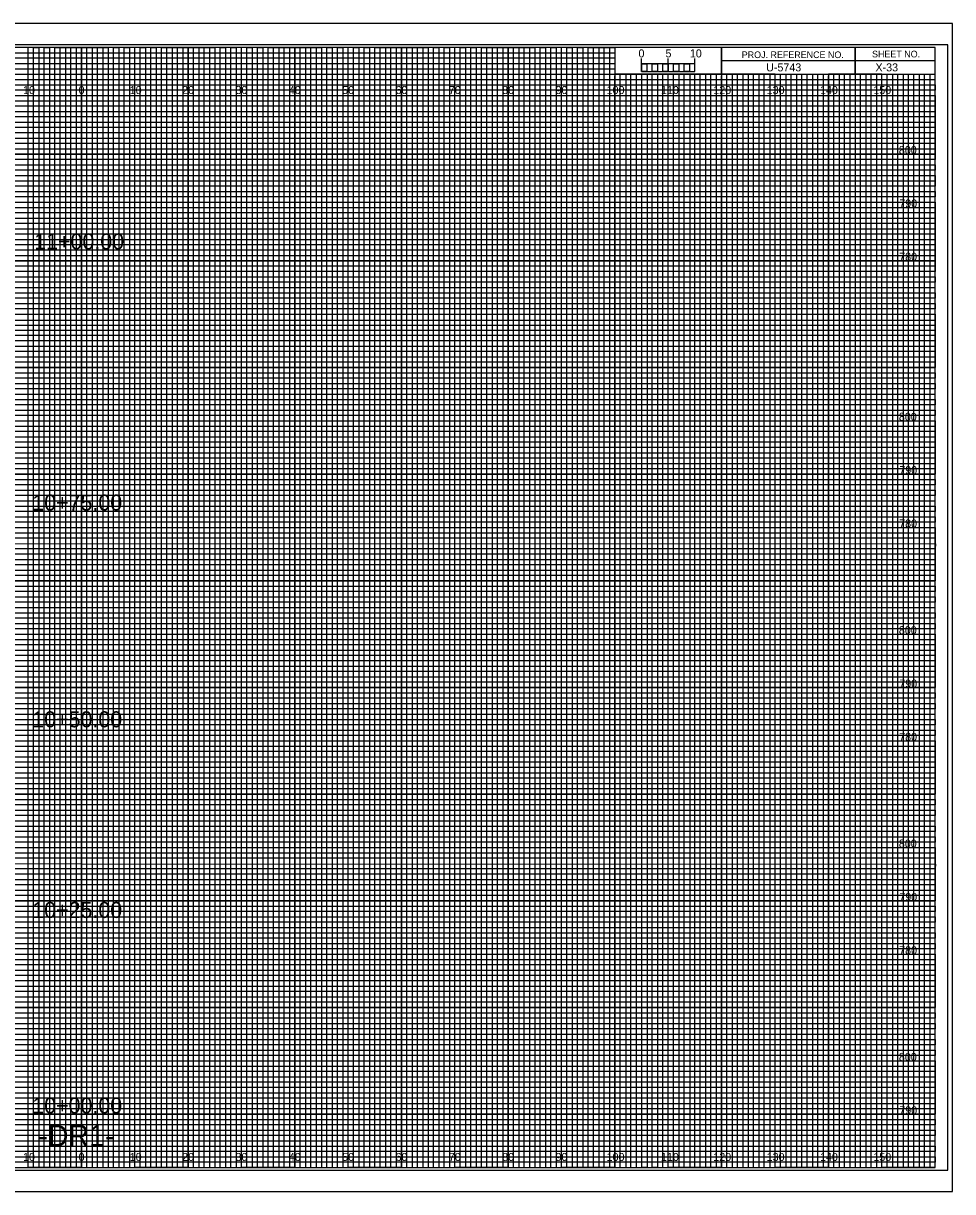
# Model space of a CAD drawing. Extents: x 9987 to 10323, y 9996 to 10214.
# Drawn here: x 10149.1 to 10323.3, y 9995.5 to 10214.5 of the extents above; entities that cross this region are included whole.
import ezdxf

# ---------------------------------------------------------------- set-up
doc = ezdxf.new("R2010")
doc.units = 0
for name, color, linetype in [('Exist Cross Section Cell', 7, 'Continuous'), ('Exist XS Center Line Elevation Label', 7, 'Continuous'), ('Exist XS Ground Line', 7, 'Continuous'), ('Prop CMT Conc Surface', 7, 'Continuous'), ('Prop CMT Concrete Structures', 7, 'Continuous'), ('Prop CMT Pvmt Course 1', 7, 'Continuous'), ('Prop CMT Pvmt Course 1 CG', 7, 'Continuous'), ('Prop CMT Pvmt Course 2', 7, 'Continuous'), ('Prop CMT Pvmt Course 3', 7, 'Continuous'), ('Prop CMT Pvmt Surface', 7, 'Continuous'), ('Prop CMT Shld Paved Course 1', 7, 'Continuous'), ('Prop CMT Shld Paved Course 2', 7, 'Continuous'), ('Prop CMT Slope Grass', 7, 'Continuous'), ('Prop CMT Subgrade Earthwork', 7, 'Continuous'), ('Prop SS Fill Line', 7, 'Continuous'), ('Prop XS Shear Point Element', 7, 'Continuous'), ('Scratch_Level_4', 7, 'Continuous')]:
    doc.layers.add(name, color=color, linetype=linetype)

msp = doc.modelspace()

# ---------------------------------------------------------------- linework, layer by layer
at = {"layer": 'Exist XS Center Line Elevation Label'}
for points in [[(10145, 10000), (10155, 10000), (10155, 10210), (10165, 10210), (10165, 10000), (10175, 10000), (10175, 10210), (10185, 10210), (10185, 10000), (10195, 10000), (10195, 10210), (10205, 10210), (10205, 10000), (10215, 10000), (10215, 10210), (10225, 10210), (10225, 10000), (10235, 10000), (10235, 10210), (10245, 10210), (10245, 10000), (10255, 10000), (10255, 10210), (10259.93, 10210), (10260, 10210), (10260, 10205), (10264.99, 10205), (10264.99, 10000), (10275, 10000), (10275, 10205), (10285, 10205), (10285, 10000), (10295, 10000), (10295, 10205), (10305, 10205), (10305, 10000), (10315, 10000), (10315, 10205)], [(10000, 10205), (10275, 10205)], [(10000, 10185), (10320, 10185), (10320, 10195), (10000, 10195)], [(10000, 10165), (10320, 10165), (10320, 10175), (10000, 10175)], [(10000, 10145), (10320, 10145), (10320, 10155), (10000, 10155)], [(10000, 10125), (10320, 10125), (10320, 10135), (10000, 10135)], [(10000, 10105), (10320, 10105), (10320, 10115), (10000, 10115)], [(10000, 10085), (10320, 10085), (10320, 10095), (10000, 10095)], [(10000, 10065), (10320, 10065), (10320, 10075), (10000, 10075)], [(10000, 10045), (10320, 10045), (10320, 10055), (10000, 10055)], [(10000, 10025), (10320, 10025), (10320, 10035), (10000, 10035)], [(10000, 10005), (10320, 10005), (10320, 10015), (10000, 10015)]]:
    msp.add_lwpolyline(points, dxfattribs=at)
at = {"layer": 'Exist XS Ground Line'}
for p, q in [((10150, 10210), (10140, 10210)), ((10150, 10000), (10150, 10210)), ((10170, 10210), (10160, 10210)), ((10160, 10210), (10160, 10000)), ((10170, 10000), (10170, 10210)), ((10190, 10210), (10180, 10210)), ((10180, 10210), (10180, 10000)), ((10190, 10000), (10190, 10210)), ((10210, 10210), (10200, 10210)), ((10200, 10210), (10200, 10000)), ((10210, 10000), (10210, 10210)), ((10230, 10210), (10220, 10210)), ((10220, 10210), (10220, 10000)), ((10230, 10000), (10230, 10210)), ((10250, 10210), (10240, 10210)), ((10240, 10210), (10240, 10000)), ((10250, 10000), (10250, 10210)), ((10260, 10210), (10260, 10000)), ((10270, 10000), (10270, 10205)), ((10290, 10205), (10280, 10205)), ((10280, 10205), (10280, 10000)), ((10290, 10000), (10290, 10205)), ((10310, 10205), (10300, 10205)), ((10300, 10205), (10300, 10000)), ((10310, 10000), (10310, 10205)), ((10160, 10000), (10150, 10000)), ((10180, 10000), (10170, 10000)), ((10200, 10000), (10190, 10000)), ((10220, 10000), (10210, 10000)), ((10240, 10000), (10230, 10000)), ((10260, 10000), (10250, 10000)), ((10280, 10000), (10270, 10000)), ((10300, 10000), (10290, 10000)), ((10320, 10000), (10310, 10000)), ((10320, 10000), (10320, 10000))]:
    msp.add_line(p, q, dxfattribs=at)
for points in [[(10000, 10200), (10320, 10200), (10320, 10190), (10000, 10190)], [(10000, 10180), (10320, 10180), (10320, 10170), (10000, 10170)], [(10000, 10160), (10320, 10160), (10320, 10150), (10000, 10150)], [(10000, 10140), (10320, 10140), (10320, 10130), (10000, 10130)], [(10000, 10120), (10320, 10120), (10320, 10110), (10000, 10110)], [(10000, 10100), (10320, 10100), (10320, 10090), (10000, 10090)], [(10000, 10080), (10320, 10080), (10320, 10070), (10000, 10070)], [(10000, 10060), (10320, 10060), (10320, 10050), (10000, 10050)], [(10000, 10040), (10320, 10040), (10320, 10030), (10000, 10030)], [(10000, 10020), (10320, 10020), (10320, 10010), (10000, 10010)]]:
    msp.add_lwpolyline(points, dxfattribs=at)
at = {"layer": 'Prop CMT Conc Surface'}
for p, q in [((10323.3, 10214.5), (9986.6, 10214.5)), ((9986.6, 9995.5), (10323.3, 9995.5))]:
    msp.add_line(p, q, dxfattribs=at)
msp.add_lwpolyline([(9986.6, 9995.5), (10323.3, 9995.5), (10323.3, 10214.5), (9986.6, 10214.5)], close=True, dxfattribs=at)
at = {"layer": 'Prop CMT Concrete Structures'}
for p, q in [((10267, 10205), (10266.01, 10205)), ((10266.01, 10205), (10266.01, 10000)), ((10267, 10000), (10267, 10205)), ((10269, 10205), (10268, 10205)), ((10268, 10205), (10268, 10000)), ((10269, 10000), (10269, 10205)), ((10266.01, 10000), (10265, 10000)), ((10268, 10000), (10267, 10000))]:
    msp.add_line(p, q, dxfattribs=at)
for points in [[(10150, 10000), (10151, 10000), (10151, 10210), (10152, 10210), (10152, 10000)], [(10152, 10000), (10153, 10000), (10153, 10210), (10154, 10210), (10154, 10000)], [(10155, 10000), (10156, 10000), (10156, 10210), (10157, 10210), (10157, 10000)], [(10157, 10000), (10158, 10000), (10158, 10210), (10159, 10210), (10159, 10000)], [(10160, 10000), (10161, 10000), (10161, 10210), (10162, 10210), (10162, 10000)], [(10162, 10000), (10163, 10000), (10163, 10210), (10164, 10210), (10164, 10000)], [(10165, 10000), (10166, 10000), (10166, 10210), (10167, 10210), (10167, 10000)], [(10167, 10000), (10168, 10000), (10168, 10210), (10169, 10210), (10169, 10000)], [(10170, 10000), (10171, 10000), (10171, 10210), (10172, 10210), (10172, 10000)], [(10172, 10000), (10173, 10000), (10173, 10210), (10174, 10210), (10174, 10000)], [(10175, 10000), (10176, 10000), (10176, 10210), (10177, 10210), (10177, 10000)], [(10177, 10000), (10178, 10000), (10178, 10210), (10179, 10210), (10179, 10000)], [(10180, 10000), (10181, 10000), (10181, 10210), (10182, 10210), (10182, 10000)], [(10182, 10000), (10183, 10000), (10183, 10210), (10184, 10210), (10184, 10000)], [(10185, 10000), (10186, 10000), (10186, 10210), (10187, 10210), (10187, 10000)], [(10187, 10000), (10188, 10000), (10188, 10210), (10189, 10210), (10189, 10000)], [(10190, 10000), (10191, 10000), (10191, 10210), (10192, 10210), (10192, 10000)], [(10192, 10000), (10193, 10000), (10193, 10210), (10194, 10210), (10194, 10000)], [(10195, 10000), (10196, 10000), (10196, 10210), (10197, 10210), (10197, 10000)], [(10197, 10000), (10198, 10000), (10198, 10210), (10199, 10210), (10199, 10000)], [(10200, 10000), (10201, 10000), (10201, 10210), (10202, 10210), (10202, 10000)], [(10202, 10000), (10203, 10000), (10203, 10210), (10204, 10210), (10204, 10000)], [(10205, 10000), (10206, 10000), (10206, 10210), (10207, 10210), (10207, 10000)], [(10207, 10000), (10208, 10000), (10208, 10210), (10209, 10210), (10209, 10000)], [(10210, 10000), (10211, 10000), (10211, 10210), (10212, 10210), (10212, 10000)], [(10212, 10000), (10213, 10000), (10213, 10210), (10214, 10210), (10214, 10000)], [(10215, 10000), (10216, 10000), (10216, 10210), (10217, 10210), (10217, 10000)], [(10217, 10000), (10218, 10000), (10218, 10210), (10219, 10210), (10219, 10000)], [(10220, 10000), (10221, 10000), (10221, 10210), (10222, 10210), (10222, 10000)], [(10222, 10000), (10223, 10000), (10223, 10210), (10224, 10210), (10224, 10000)], [(10225, 10000), (10226, 10000), (10226, 10210), (10227, 10210), (10227, 10000)], [(10227, 10000), (10228, 10000), (10228, 10210), (10229, 10210), (10229, 10000)], [(10230, 10000), (10231, 10000), (10231, 10210), (10232, 10210), (10232, 10000)], [(10232, 10000), (10233, 10000), (10233, 10210), (10234, 10210), (10234, 10000)], [(10235, 10000), (10236, 10000), (10236, 10210), (10237, 10210), (10237, 10000)], [(10237, 10000), (10238, 10000), (10238, 10210), (10239, 10210), (10239, 10000)], [(10240, 10000), (10241, 10000), (10241, 10210), (10242, 10210), (10242, 10000)], [(10242, 10000), (10243, 10000), (10243, 10210), (10244, 10210), (10244, 10000)], [(10245, 10000), (10246, 10000), (10246, 10210), (10247, 10210), (10247, 10000)], [(10247, 10000), (10248, 10000), (10248, 10210), (10249, 10210), (10249, 10000)], [(10250, 10000), (10251, 10000), (10251, 10210), (10252, 10210), (10252, 10000)], [(10252, 10000), (10253, 10000), (10253, 10210), (10254, 10210), (10254, 10000)], [(10255, 10000), (10256, 10000), (10256, 10210), (10257, 10210), (10257, 10000)], [(10257, 10000), (10258, 10000), (10258, 10210), (10259, 10210), (10259, 10000)], [(10260, 10000), (10261, 10000), (10261, 10205), (10262.02, 10205), (10262.02, 10000)], [(10262, 10000), (10263, 10000), (10263, 10205), (10263.99, 10205), (10263.99, 10000)], [(10270, 10000), (10270.98, 10000), (10270.98, 10205), (10272, 10205), (10272, 10000)], [(10272, 10000), (10273, 10000), (10273, 10205), (10274.05, 10205), (10274.05, 10000)], [(10275, 10000), (10276, 10000), (10276, 10205), (10277, 10205), (10277, 10000)], [(10277, 10000), (10278, 10000), (10278, 10205), (10279, 10205), (10279, 10000)], [(10280, 10000), (10281, 10000), (10281, 10205), (10282, 10205), (10282, 10000)], [(10282, 10000), (10283, 10000), (10283, 10205), (10284, 10205), (10284, 10000)], [(10285, 10000), (10286, 10000), (10286, 10205), (10287, 10205), (10287, 10000)], [(10287, 10000), (10288, 10000), (10288, 10205), (10289, 10205), (10289, 10000)], [(10290, 10000), (10291, 10000), (10291, 10205), (10292, 10205), (10292, 10000)], [(10292, 10000), (10293, 10000), (10293, 10205), (10294, 10205), (10294, 10000)], [(10295, 10000), (10296, 10000), (10296, 10205), (10297, 10205), (10297, 10000)], [(10297, 10000), (10298, 10000), (10298, 10205), (10299, 10205), (10299, 10000)], [(10300, 10000), (10301, 10000), (10301, 10205), (10302, 10205), (10302, 10000)], [(10302, 10000), (10303, 10000), (10303, 10205), (10304, 10205), (10304, 10000)], [(10305, 10000), (10306, 10000), (10306, 10205), (10307, 10205), (10307, 10000)], [(10307, 10000), (10308, 10000), (10308, 10205), (10309, 10205), (10309, 10000)], [(10310, 10000), (10311, 10000), (10311, 10205), (10312, 10205), (10312, 10000)], [(10312, 10000), (10313, 10000), (10313, 10205), (10314, 10205), (10314, 10000)], [(10315, 10000), (10316, 10000), (10316, 10205), (10317, 10205), (10317, 10000)], [(10317, 10000), (10318, 10000), (10318, 10205), (10319, 10205), (10319, 10000)]]:
    msp.add_lwpolyline(points, dxfattribs=at)
at = {"layer": 'Prop CMT Pvmt Course 1'}
msp.add_lwpolyline([(9989.2, 9999.5), (10322.4, 9999.5), (10322.4, 10210.5), (9989.2, 10210.5)], close=True, dxfattribs=at)
at = {"layer": 'Prop CMT Pvmt Course 1 CG'}
msp.add_lwpolyline([(9986.6, 9995.5), (10323.3, 9995.5), (10323.3, 10214.5), (9986.6, 10214.5)], close=True, dxfattribs=at)
at = {"layer": 'Prop CMT Pvmt Course 2'}
for p, q in [((10000, 10209), (10260, 10209)), ((10260, 10207.98), (10000, 10207.98)), ((10260, 10209), (10260, 10207.98)), ((10000, 10207), (10260, 10207)), ((10260, 10205.89), (10000, 10205.89)), ((10260, 10207), (10260, 10205.89)), ((10000, 10204), (10320, 10204))]:
    msp.add_line(p, q, dxfattribs=at)
for points in [[(10000, 10203), (10270, 10203), (10320, 10203), (10320, 10202), (10000, 10202)], [(10000, 10201), (10320, 10201), (10320, 10199), (10000, 10199)], [(10000, 10198), (10320, 10198), (10320, 10197), (10000, 10196.98)], [(10000, 10196), (10320, 10196), (10320, 10194), (10000, 10194)], [(10000, 10193), (10320, 10193), (10320, 10192), (10000, 10192)], [(10000, 10191), (10320, 10191), (10320, 10189), (10000, 10189)], [(10000, 10188), (10320, 10188), (10320, 10187), (10000, 10187)], [(10000, 10186), (10320, 10186), (10320, 10184), (10000, 10184)], [(10000, 10183), (10320, 10183), (10320, 10182), (10000, 10182)], [(10000, 10181), (10320, 10181), (10320, 10179), (10000, 10179)], [(10000, 10178), (10320, 10178), (10320, 10177), (10000, 10177)], [(10000, 10176), (10320, 10176), (10320, 10173.95), (10320, 10173), (10320, 10172), (10000, 10172)], [(10000, 10174), (10320, 10174), (10320, 10173), (10000, 10173)], [(10000, 10171), (10320, 10171), (10320, 10169), (10000, 10169.03)], [(10000, 10169.03), (10320, 10169), (10320, 10168), (10000, 10168)], [(10000, 10167), (10320, 10167), (10320, 10166), (10000, 10166)], [(10000, 10164), (10320, 10164), (10320, 10163), (10000, 10163)], [(10000, 10162), (10320, 10162), (10320, 10161), (10000, 10161)], [(9999.93, 10158.89), (10320, 10158.89), (10320, 10157.88), (9999.93, 10157.88)], [(10000, 10157), (10320, 10157), (10320, 10156), (10000, 10156)], [(10000, 10154), (10320, 10154), (10320, 10153), (10000, 10153)], [(10000, 10152), (10320, 10152), (10320, 10151), (10000, 10151)], [(10000, 10149), (10320, 10149), (10320, 10148), (10000, 10148)], [(10000, 10147), (10320, 10147), (10320, 10146), (10000, 10146)], [(10000, 10144), (10320, 10144), (10320, 10143), (10000, 10143)], [(10000, 10142), (10320, 10142), (10320, 10141), (10000, 10141)], [(10000, 10139), (10320, 10139), (10319.99, 10137.98), (10000, 10138)], [(10000, 10137), (10320, 10137), (10320, 10136), (10000, 10136)], [(10000, 10134), (10320, 10134), (10320, 10133), (10000, 10133)], [(10000, 10132), (10320, 10132), (10320, 10131), (10000, 10131)], [(10000, 10129), (10320, 10129), (10320, 10128), (10000, 10128)], [(10000, 10127), (10320, 10127), (10320, 10126), (10000, 10126)], [(10000, 10124), (10320, 10124), (10320, 10123), (10000, 10123)], [(10000, 10122), (10320, 10122), (10320, 10121), (10000, 10121)], [(10000, 10119), (10320, 10119), (10320, 10118), (10000, 10118)], [(10000, 10116.99), (10320.07, 10116.91), (10320, 10116), (10000, 10116)], [(10000, 10114), (10320, 10114), (10320, 10113), (10000, 10113)], [(10000, 10112), (10320, 10112), (10320, 10111), (10000, 10111)], [(10000, 10109), (10320, 10109), (10320, 10108), (10000, 10108)], [(10000, 10107), (10320, 10107), (10320, 10106), (10000, 10106)], [(10000, 10104), (10320, 10104), (10320, 10103), (10000, 10103)], [(10000, 10102), (10320, 10102), (10320, 10101), (10000, 10101)], [(10000, 10099), (10320, 10099), (10320, 10098), (10000, 10098)], [(10000, 10097), (10320, 10097), (10320, 10096), (10000, 10096)], [(10000, 10094), (10320, 10094), (10320, 10093), (10000, 10093)], [(10000, 10092), (10320, 10092), (10320, 10091), (10000, 10091)], [(10000, 10089), (10320, 10089), (10320, 10088), (10000, 10088)], [(10000, 10087), (10320, 10087), (10320, 10086), (10000, 10086)], [(10000, 10084), (10320, 10084), (10320, 10083), (10000, 10083)], [(10000, 10082), (10320, 10082), (10320, 10081), (10000, 10081)], [(10000, 10079), (10320, 10079), (10319.99, 10077.98), (10000, 10078)], [(10000, 10077), (10320, 10077), (10320, 10076), (10000, 10076)], [(10000, 10074), (10320, 10074), (10320, 10073), (10000, 10073)], [(10000, 10072), (10320, 10072), (10320, 10071), (10000, 10071)], [(10000, 10069), (10320, 10069), (10320, 10068), (10000, 10068)], [(10000, 10067), (10320, 10067), (10320, 10066), (10000, 10066)], [(10000, 10064), (10320, 10064), (10320, 10063), (10000, 10063)], [(10000, 10062), (10320, 10062), (10320, 10061), (10000, 10061)], [(10000, 10059), (10320, 10059), (10320, 10058), (10000, 10058)], [(10000, 10056.99), (10320.07, 10056.91), (10320, 10056), (10000, 10056)], [(10000, 10054), (10320, 10054), (10320, 10053), (10000, 10053)], [(10000, 10052), (10320, 10052), (10320, 10051), (10000, 10051)], [(10000, 10049), (10320, 10049), (10320, 10048), (10000, 10048)], [(10000, 10047), (10320, 10047), (10320, 10046), (10000, 10046)], [(10000, 10044), (10320, 10044), (10320, 10043), (10000, 10043)], [(10000, 10042), (10320, 10042), (10320, 10041), (10000, 10041)], [(10000, 10039), (10320, 10039), (10320, 10038), (10000, 10038)], [(10000, 10037), (10320, 10037), (10320, 10036), (10000, 10036)], [(10000, 10034), (10320, 10034), (10320, 10033), (10000, 10033)], [(10000, 10032), (10320, 10032), (10320, 10031), (10000, 10031)], [(10000, 10029), (10320, 10029), (10320, 10028), (10000, 10028)], [(10000, 10027), (10320, 10027), (10320, 10026), (10000, 10026)], [(10000, 10024), (10320, 10024), (10320, 10023), (10000, 10023)], [(10000, 10022), (10320, 10022), (10320, 10021), (10000, 10021)], [(10000, 10019), (10320, 10019), (10320, 10018), (10000, 10018)], [(10000, 10017), (10320, 10017), (10320, 10016), (10000, 10016)], [(10000, 10014), (10320, 10014), (10320, 10013), (10000, 10013)], [(10000, 10012), (10320, 10012), (10320, 10011), (10000, 10011)], [(10000, 10009), (10320, 10009), (10320, 10008), (10000, 10008)], [(10000, 10007), (10320, 10007), (10320, 10006), (10000, 10006)], [(10000, 10004), (10320, 10004), (10320, 10003), (10000, 10003)], [(10000, 10002), (10320, 10002), (10320, 10001), (10000, 10001)]]:
    msp.add_lwpolyline(points, dxfattribs=at)
at = {"layer": 'Prop CMT Pvmt Course 3'}
for p, q in [((10305, 10210), (10305, 10205)), ((10305, 10205), (10305, 10210)), ((10280, 10207.5), (10280, 10205)), ((10320, 10207.49), (10280, 10207.49)), ((10280, 10205), (10320, 10205))]:
    msp.add_line(p, q, dxfattribs=at)
for points in [[(10320, 10210), (10000, 10210), (10000, 10000), (10320, 10000)], [(10280, 10210), (10260, 10210), (10260, 10205.03), (10280, 10205.03)], [(10320, 10210), (10280, 10210), (10280, 10205), (10320, 10205)]]:
    msp.add_lwpolyline(points, close=True, dxfattribs=at)
at = {"layer": 'Prop SS Fill Line'}
for p, q in [((10265, 10205.49), (10265, 10207.9)), ((10265, 10206.9), (10265, 10207.9)), ((10270, 10205.49), (10270, 10207.9)), ((10275, 10205.49), (10275, 10207.9)), ((10275, 10206.9), (10275, 10207.9))]:
    msp.add_line(p, q, dxfattribs=at)
for points in [[(10275, 10206.9), (10265, 10206.9), (10265, 10205.49), (10275, 10205.49)], [(10265, 10206.9), (10266, 10206.9), (10266, 10205.49), (10265, 10205.49)], [(10267, 10206.9), (10268, 10206.9), (10268, 10205.49), (10267, 10205.49)], [(10269, 10206.9), (10270, 10206.9), (10270, 10205.49), (10269, 10205.49)], [(10271, 10206.9), (10272, 10206.9), (10272, 10205.49), (10271, 10205.49)], [(10273, 10206.9), (10274, 10206.9), (10274, 10205.49), (10273, 10205.49)]]:
    msp.add_lwpolyline(points, close=True, dxfattribs=at)
at = {"layer": 'Prop XS Shear Point Element'}
for p, q in [((10150, 10000), (10150, 10210)), ((10160, 10000), (10160, 10210)), ((10170, 10000), (10170, 10210)), ((10180, 10000), (10180, 10210)), ((10190, 10000), (10190, 10210)), ((10200, 10000), (10200, 10210)), ((10210, 10000), (10210, 10210)), ((10220, 10000), (10220, 10210)), ((10230, 10000), (10230, 10210)), ((10240, 10000), (10240, 10210)), ((10250, 10000), (10250, 10210)), ((10260, 10000), (10260, 10204.69)), ((10270, 10000), (10270, 10204.69)), ((10280, 10000), (10280, 10204.69)), ((10290, 10000), (10290, 10204.69)), ((10300, 10000), (10300, 10204.69)), ((10310, 10000), (10310, 10204.69)), ((10000, 10200), (10320, 10200)), ((10000, 10190), (10320, 10190)), ((10000, 10180), (10320, 10180)), ((10000, 10170), (10320, 10170)), ((10000, 10160), (10320, 10160)), ((10000, 10150), (10320, 10150)), ((10000, 10140), (10320, 10140)), ((10000, 10130), (10320, 10130)), ((10000, 10120), (10320, 10120)), ((10000, 10110), (10320, 10110)), ((10000, 10100), (10320, 10100)), ((10000, 10090), (10320, 10090)), ((10000, 10080), (10320, 10080)), ((10000, 10070), (10320, 10070)), ((10000, 10060), (10320, 10060)), ((10000, 10050), (10320, 10050)), ((10000, 10040), (10320, 10040)), ((10000, 10030), (10320, 10030)), ((10000, 10020), (10320, 10020)), ((10000, 10010), (10320, 10010))]:
    msp.add_line(p, q, dxfattribs=at)

# ---------------------------------------------------------------- texts
at = {"layer": 'Exist Cross Section Cell'}
for s, p in [('10', (10149.04, 10201.25)), ('0', (10159.45, 10201.25)), ('10', (10169.04, 10201.25)), ('20', (10178.86, 10201.25)), ('30', (10188.86, 10201.25)), ('40', (10198.86, 10201.25)), ('50', (10208.86, 10201.25)), ('60', (10218.86, 10201.25)), ('70', (10228.86, 10201.25)), ('80', (10238.86, 10201.25)), ('90', (10248.86, 10201.25)), ('100', (10258.44, 10201.25)), ('110', (10268.62, 10201.25)), ('120', (10278.44, 10201.25)), ('130', (10288.44, 10201.25)), ('140', (10298.44, 10201.25)), ('150', (10308.44, 10201.25)), ('10', (10149.04, 10001.25)), ('0', (10159.45, 10001.25)), ('10', (10169.04, 10001.25)), ('20', (10178.86, 10001.25)), ('30', (10188.86, 10001.25)), ('40', (10198.86, 10001.25)), ('50', (10208.86, 10001.25)), ('60', (10218.86, 10001.25)), ('70', (10228.86, 10001.25)), ('80', (10238.86, 10001.25)), ('90', (10248.86, 10001.25)), ('100', (10258.44, 10001.25)), ('110', (10268.62, 10001.25)), ('120', (10278.44, 10001.25)), ('130', (10288.44, 10001.25)), ('140', (10298.44, 10001.25)), ('150', (10308.44, 10001.25))]:
    msp.add_text(s, height=1.5, dxfattribs=at).set_placement(p)
at = {"layer": 'Prop CMT Pvmt Course 3'}
for s, p in [('PROJ. REFERENCE NO.', (10283.77, 10207.99)), ('SHEET NO.', (10308.19, 10208.12))]:
    msp.add_text(s, height=1.25, dxfattribs=at).set_placement(p)
at = {"layer": 'Prop CMT Pvmt Surface'}
for s, p in [('800', (10313.22, 10190)), ('790', (10313.3, 10180)), ('780', (10313.28, 10170)), ('800', (10313.22, 10140)), ('790', (10313.3, 10130)), ('780', (10313.28, 10120)), ('800', (10313.22, 10100)), ('790', (10313.3, 10090)), ('780', (10313.28, 10080)), ('800', (10313.22, 10060)), ('790', (10313.3, 10050)), ('780', (10313.28, 10040)), ('800', (10313.22, 10020)), ('790', (10313.3, 10010))]:
    msp.add_text(s, height=1.5, dxfattribs=at).set_placement(p)
at = {"layer": 'Prop CMT Shld Paved Course 1'}
msp.add_text('U-5743', height=1.5, dxfattribs=at).set_placement((10288.34, 10205.5))
at = {"layer": 'Prop CMT Shld Paved Course 2'}
for s, p in [('5', (10269.47, 10208.12)), ('10', (10274.04, 10208.12))]:
    msp.add_text(s, height=1.5, dxfattribs=at).set_placement(p)
at = {"layer": 'Prop CMT Slope Grass'}
msp.add_text('X-33', height=1.5, dxfattribs=at).set_placement((10308.83, 10205.5))
at = {"layer": 'Prop CMT Subgrade Earthwork'}
for s, p in [('11+00.00', (10151.13, 10172.13)), ('10+75.00', (10150.77, 10123.17)), ('10+50.00', (10150.77, 10082.54)), ('10+25.00', (10150.77, 10046.8)), ('10+00.00', (10150.77, 10010.16))]:
    msp.add_text(s, height=3, dxfattribs=at).set_placement(p)
at = {"layer": 'Prop SS Fill Line'}
msp.add_text('0', height=1.5, dxfattribs=at).set_placement((10264.41, 10208.12))
at = {"layer": 'Scratch_Level_4'}
msp.add_text('-DR1-', height=4, dxfattribs=at).set_placement((10151.91, 10004))

doc.saveas('drawing.dxf')
